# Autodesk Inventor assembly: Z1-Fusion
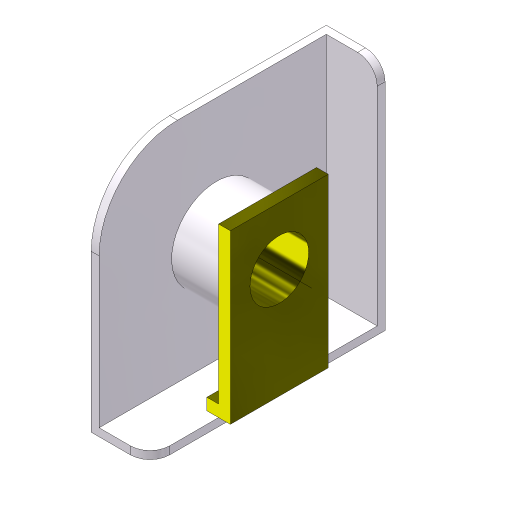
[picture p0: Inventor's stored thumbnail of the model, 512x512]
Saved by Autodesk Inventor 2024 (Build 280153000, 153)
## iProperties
Company: ATC
Created: 2023-03
Part Number: Z1-Fusion
Document SubType Name: Assembly
Designer: Andrzej Jaskulski
Checked By: A.J.
Engr Approved By: Andrzej Jaskulski
Mfg Approved By: Andrzej Jaskulski
Authority: A.J.
Title: A.J.: Kurs R2024-MEP
Author: Andrzej Jaskulski
Revision Number: 1/24
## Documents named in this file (3)
- C:\Users\AndJas\Documents\R2024-MEP\Obszar roboczy\FUSION\Z1-Fusion.iam
- C:\Users\AndJas\Documents\R2024-MEP\Obszar roboczy\FUSION\Z1-Fusion-WSP.ipt
- C:\Users\AndJas\Documents\R2024-MEP\Obszar roboczy\FUSION\Z1-Fusion-ZAMEK.ipt
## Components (2 placed, 2 different names)
1. Z1-Fusion-WSP:1 — Sztywne:1
2. Z1-Fusion-ZAMEK:1 — Sztywne:1
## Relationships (1: WeldJoint 1)
- Sztywne:1 [WeldJoint]: Z1-Fusion-WSP:1 ↔ Z1-Fusion-ZAMEK:1
